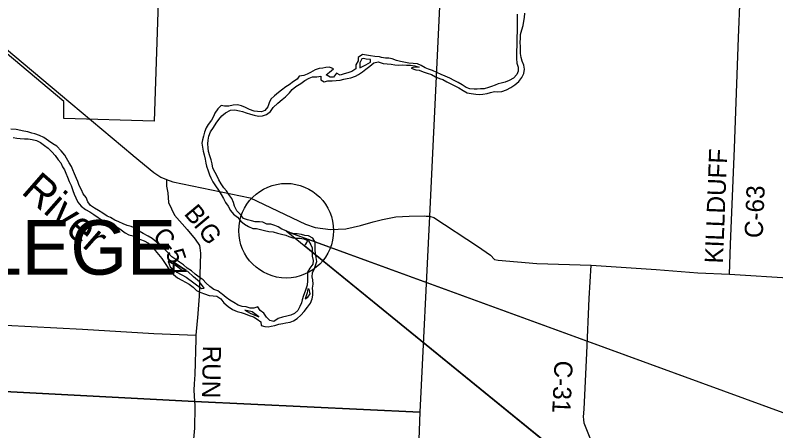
# Model space of a CAD drawing. Extents: x 41.3 to 81.6, y -19.3 to 2.7.
# Drawn here: x 46.925 to 48.932, y -1.162 to -0.064 of the extents above; entities that cross this region are included whole.
import ezdxf

# ---------------------------------------------------------------- set-up
doc = ezdxf.new("R2010")
doc.units = 0
for name, color, linetype in [('Default', 7, 'Continuous'), ('GM_X_Corporation', 7, 'Continuous'), ('GM_X_County_Road', 7, 'Continuous'), ('GM_X_County_Road_Text', 7, 'Continuous'), ('GM_X_Major_River', 7, 'Continuous'), ('GM_X_Major_River_Text', 7, 'Continuous'), ('GM_X_State_Route', 7, 'Continuous'), ('GM_X_Township', 7, 'Continuous'), ('GM_X_Township_Road', 7, 'Continuous'), ('GM_X_Township_Text', 7, 'Continuous')]:
    doc.layers.add(name, color=color, linetype=linetype)

msp = doc.modelspace()

# ---------------------------------------------------------------- linework, layer by layer
at = {"layer": 'Default'}
for p, q in [((47.6399, -0.6336), (50.5165, -2.9781)), ((47.6514, -0.6388), (50.5165, -1.6863))]:
    msp.add_line(p, q, dxfattribs=at)
msp.add_lwpolyline([(47.6983, -0.6559), (50.5165, -1.6863), (50.5165, -2.9781), (47.6883, -0.6731)], dxfattribs=at)
msp.add_circle((47.6399, -0.6336), 0.125, dxfattribs=at)
msp.add_arc((47.6399, -0.6336), 0.0625, 320.8199, 339.1082, dxfattribs=at)
at = {"layer": 'GM_X_Corporation'}
msp.add_lwpolyline([(46.584, 0.4876), (46.608, 0.4783), (46.619, 0.799), (47.3288, 0.7822), (47.2918, -0.3441), (47.053, -0.3369), (47.053, -0.2918), (46.8252, -0.1011), (46.7581, -0.0438), (46.7215, -0.0005), (46.7256, 0.0209), (46.722, 0.0646), (46.7171, 0.1029), (46.7053, 0.1736), (46.6837, 0.2398), (46.6465, 0.2782), (46.6014, 0.293), (46.6062, 0.436), (46.6004, 0.4311), (46.5985, 0.4242), (46.5815, 0.4287), (46.5709, 0.4515)], close=True, dxfattribs=at)
at = {"layer": 'GM_X_County_Road'}
for points in [[(48.8102, -0.7486), (48.813, -0.6703), (48.823, -0.4156), (48.8336, -0.1239), (48.8383, -0.0159), (48.8447, 0.1605), (48.8484, 0.2147), (48.8509, 0.225), (48.8521, 0.23), (48.8515, 0.235)], [(47.3243, -0.4981), (47.3242, -0.516), (47.3271, -0.5333), (47.3296, -0.5586), (47.3454, -0.5926), (47.3787, -0.6308), (47.3999, -0.6561), (47.4107, -0.6723), (47.4117, -0.679)], [(47.4117, -0.679), (47.4136, -0.6925), (47.41, -0.8064), (47.4058, -0.8639)], [(48.4513, -1.2042), (48.4266, -1.1421), (48.4254, -1.1325), (48.4248, -1.1257), (48.4262, -1.1052), (48.4333, -0.9576), (48.4399, -0.8126), (48.445, -0.7243)], [(47.4058, -0.8639), (47.4052, -0.8717), (47.4017, -0.91), (47.4013, -0.9199), (47.3989, -1.0139), (47.397, -1.0382), (47.3962, -1.0553), (47.3982, -1.085), (47.3987, -1.0945)], [(47.3987, -1.0945), (47.3989, -1.0986), (47.3981, -1.1557), (47.3902, -1.2438)]]:
    msp.add_lwpolyline(points, dxfattribs=at)
at = {"layer": 'GM_X_Major_River'}
for points in [[(47.8928, -0.1906), (47.8956, -0.1919), (47.9065, -0.1929), (47.9171, -0.1932), (47.927, -0.1952), (47.9369, -0.1965), (47.9475, -0.1953), (47.9574, -0.1959), (47.968, -0.196), (47.9795, -0.1976), (47.9907, -0.2012), (47.9745, -0.2024), (47.9697, -0.2045), (47.9824, -0.2081), (47.9905, -0.2091), (48.0016, -0.214), (48.0121, -0.2169), (48.023, -0.2208), (48.0342, -0.2273), (48.0444, -0.2315), (48.0531, -0.2341), (48.0636, -0.2402), (48.0726, -0.245), (48.085, -0.2508), (48.0959, -0.256), (48.1068, -0.2628), (48.1173, -0.2689), (48.1282, -0.2712), (48.1401, -0.2728), (48.1506, -0.2735), (48.1593, -0.2732), (48.1702, -0.2707), (48.1788, -0.2681), (48.1894, -0.2653), (48.1981, -0.2666), (48.2093, -0.2653), (48.2215, -0.2609), (48.2324, -0.2554), (48.2436, -0.2484), (48.2536, -0.2392), (48.2616, -0.2289), (48.2671, -0.2183), (48.2687, -0.2068), (48.2668, -0.1965), (48.263, -0.1859), (48.2602, -0.1757), (48.2586, -0.1651), (48.258, -0.1551), (48.258, -0.1471), (48.2577, -0.1362), (48.2581, -0.125), (48.2587, -0.1147), (48.2617, -0.1029), (48.2652, -0.0916), (48.2672, -0.0801), (48.2688, -0.0698), (48.2698, -0.0586)], [(48.2493, -0.0614), (48.2493, -0.0701), (48.2495, -0.0807), (48.2492, -0.0926), (48.2491, -0.1092), (48.2485, -0.1205), (48.2484, -0.1285), (48.2487, -0.1368), (48.2487, -0.1458), (48.248, -0.157), (48.248, -0.1788), (48.2489, -0.1907), (48.2521, -0.2013), (48.2524, -0.2122), (48.2485, -0.2205), (48.2398, -0.2301), (48.2283, -0.2365), (48.2177, -0.2407), (48.2071, -0.2435), (48.1991, -0.2454), (48.1911, -0.2492), (48.1821, -0.2524), (48.1741, -0.2553), (48.1625, -0.2588), (48.1523, -0.2587), (48.1443, -0.2594), (48.1363, -0.2593), (48.1247, -0.259), (48.1145, -0.2554), (48.104, -0.248), (48.0934, -0.2422), (48.0832, -0.2367), (48.072, -0.2309), (48.0595, -0.2254), (48.0489, -0.2209), (48.0377, -0.2154), (48.0262, -0.2106), (48.0154, -0.2067), (48.007, -0.2028), (47.9958, -0.1967), (47.9862, -0.1925), (47.9754, -0.1915), (47.9635, -0.1905), (47.9417, -0.1866), (47.9309, -0.1837), (47.9193, -0.1795), (47.911, -0.1778), (47.9017, -0.1775), (47.8918, -0.1755), (47.8861, -0.1741)], [(47.8861, -0.1741), (47.8736, -0.1728), (47.8627, -0.1715), (47.8515, -0.1693), (47.8413, -0.168), (47.8301, -0.1763), (47.8298, -0.1846), (47.824, -0.1955), (47.8237, -0.2061), (47.8134, -0.2125), (47.8029, -0.2163), (47.7929, -0.2189), (47.7827, -0.2227), (47.7725, -0.2172), (47.7651, -0.2281), (47.7555, -0.2278), (47.7456, -0.2214), (47.7543, -0.2143), (47.7648, -0.206), (47.7543, -0.2012), (47.7447, -0.2025), (47.7364, -0.204), (47.7271, -0.205), (47.7162, -0.2088), (47.7037, -0.2155), (47.6954, -0.2197), (47.6861, -0.2235), (47.6743, -0.2251), (47.6692, -0.2335), (47.6589, -0.2389), (47.6477, -0.2485), (47.6388, -0.2536), (47.6279, -0.2623), (47.6192, -0.268), (47.6093, -0.277), (47.5997, -0.2856)], [(47.8397, -0.1798), (47.8339, -0.1904), (47.8345, -0.2035), (47.8502, -0.1949)], [(47.8502, -0.1949), (47.8627, -0.1882), (47.8621, -0.1815), (47.8509, -0.1805), (47.8442, -0.1789), (47.8397, -0.1798)], [(47.6058, -0.3084), (47.6182, -0.2962), (47.6288, -0.2873), (47.6378, -0.2802), (47.649, -0.269), (47.6557, -0.2607), (47.6653, -0.2524), (47.6781, -0.245), (47.6893, -0.237), (47.7002, -0.2303), (47.7092, -0.2274), (47.7203, -0.2268), (47.7312, -0.2255), (47.7315, -0.2348), (47.7398, -0.24), (47.7501, -0.2377), (47.7613, -0.2371), (47.7718, -0.2368), (47.7827, -0.2359), (47.792, -0.2333), (47.8006, -0.2317), (47.8105, -0.2295), (47.8224, -0.2253), (47.831, -0.2209), (47.8412, -0.2138), (47.8499, -0.2071), (47.8604, -0.1991), (47.8713, -0.1898), (47.8822, -0.1869), (47.8928, -0.1906)], [(47.5997, -0.2856), (47.5952, -0.2959), (47.5917, -0.3061), (47.5837, -0.3161), (47.575, -0.3193), (47.5639, -0.3189), (47.5549, -0.3173), (47.5434, -0.3135), (47.5322, -0.308), (47.5223, -0.3038), (47.5114, -0.3006), (47.4996, -0.3015), (47.4881, -0.3047), (47.4769, -0.3041), (47.4679, -0.3031), (47.459, -0.3114), (47.4513, -0.3226), (47.4484, -0.3319), (47.4426, -0.3419), (47.4337, -0.3531), (47.4289, -0.3614), (47.424, -0.3729), (47.4215, -0.3835), (47.4192, -0.3931), (47.4176, -0.4024), (47.4192, -0.413), (47.4211, -0.4233), (47.4233, -0.4329), (47.4262, -0.4445), (47.4281, -0.4554), (47.4297, -0.4634), (47.4338, -0.4753), (47.4377, -0.4855), (47.4412, -0.4935), (47.4463, -0.5048), (47.4533, -0.5154), (47.4609, -0.5263), (47.4683, -0.5378), (47.474, -0.5484), (47.4801, -0.559), (47.4865, -0.569), (47.4932, -0.5799), (47.5005, -0.5898), (47.5111, -0.5975), (47.52, -0.6085), (47.5299, -0.6162), (47.5401, -0.6226), (47.5516, -0.6274), (47.5619, -0.6274), (47.5718, -0.6303), (47.5823, -0.6329), (47.5938, -0.6355), (47.6054, -0.6365), (47.6165, -0.6404), (47.6274, -0.6426), (47.6386, -0.6452), (47.6469, -0.6491), (47.6575, -0.6523), (47.6661, -0.6532), (47.6763, -0.6529), (47.6866, -0.6552), (47.6987, -0.6607), (47.7051, -0.6709), (47.7086, -0.679), (47.7083, -0.6892), (47.7082, -0.7005), (47.7111, -0.712), (47.7104, -0.7219), (47.7024, -0.7322), (47.6964, -0.7428), (47.6957, -0.7543), (47.6957, -0.7659), (47.695, -0.7771), (47.6928, -0.7857), (47.6899, -0.7937), (47.6857, -0.8046), (47.6822, -0.8159), (47.6799, -0.8239), (47.6758, -0.8341), (47.6706, -0.8444), (47.6617, -0.8527), (47.6518, -0.8569), (47.6415, -0.8597), (47.6303, -0.8623), (47.6191, -0.8655), (47.6073, -0.8735), (47.5964, -0.8706), (47.5875, -0.8616), (47.5811, -0.8513), (47.5709, -0.8446), (47.5651, -0.8346), (47.5546, -0.8385), (47.545, -0.8384), (47.5344, -0.8349), (47.5239, -0.8336), (47.5127, -0.8301), (47.5018, -0.8233), (47.491, -0.8175), (47.4811, -0.8098), (47.4708, -0.8011), (47.468, -0.7995)], [(47.457, -0.8068), (47.467, -0.8136), (47.4756, -0.8242), (47.4865, -0.8342), (47.4983, -0.8416), (47.5101, -0.8467), (47.521, -0.8493), (47.5319, -0.8529), (47.5424, -0.8577), (47.5533, -0.8612), (47.5635, -0.867), (47.5728, -0.8747), (47.5734, -0.884), (47.5836, -0.8863), (47.5922, -0.8873), (47.6006, -0.8857), (47.6095, -0.8838), (47.6204, -0.8809), (47.6306, -0.879), (47.6389, -0.8774), (47.6501, -0.8751), (47.6591, -0.8716), (47.669, -0.8659), (47.6783, -0.8566), (47.6876, -0.8467), (47.6959, -0.8354), (47.7039, -0.8246), (47.7081, -0.814), (47.7103, -0.8037), (47.71, -0.7935), (47.7097, -0.7854), (47.7113, -0.7752), (47.7101, -0.7636), (47.7082, -0.7556), (47.7091, -0.745), (47.7149, -0.7338), (47.7184, -0.7232), (47.7204, -0.7152), (47.7191, -0.7046), (47.7175, -0.694), (47.7159, -0.6838), (47.716, -0.6642), (47.7105, -0.6533), (47.6984, -0.6469), (47.6888, -0.6459), (47.6802, -0.644), (47.669, -0.6417), (47.6607, -0.6414), (47.6514, -0.6388), (47.6399, -0.6336), (47.6284, -0.6298), (47.6191, -0.6234), (47.6102, -0.6201), (47.599, -0.616), (47.5891, -0.6159), (47.5779, -0.6111), (47.5692, -0.6098), (47.5581, -0.6098), (47.5481, -0.6079), (47.5373, -0.6046), (47.5274, -0.6014), (47.5194, -0.5908), (47.5098, -0.5809), (47.5037, -0.569), (47.5009, -0.5594), (47.4961, -0.5485), (47.4888, -0.5375), (47.4824, -0.5279), (47.4757, -0.5199), (47.468, -0.5096), (47.4623, -0.4987), (47.4575, -0.4894), (47.4521, -0.4794), (47.4466, -0.4682), (47.4441, -0.457), (47.4419, -0.4461), (47.4387, -0.4361), (47.4352, -0.4246), (47.4336, -0.4146), (47.433, -0.4041), (47.4343, -0.3941), (47.4359, -0.3835), (47.4404, -0.372), (47.448, -0.3605), (47.4554, -0.3496), (47.4621, -0.34), (47.4698, -0.3297), (47.4801, -0.322), (47.4929, -0.315), (47.5047, -0.314), (47.5165, -0.3166), (47.5248, -0.3189), (47.5341, -0.3224), (47.5456, -0.326), (47.5549, -0.3285), (47.5664, -0.3305), (47.5773, -0.3302), (47.5882, -0.3263), (47.5984, -0.3183), (47.6058, -0.3084)], [(47.1235, -0.5672), (47.1159, -0.5569), (47.112, -0.546), (47.1041, -0.5357), (47.0999, -0.5254), (47.0932, -0.5145), (47.0897, -0.5036), (47.0862, -0.4956), (47.0808, -0.4837), (47.0766, -0.4725), (47.0735, -0.4642), (47.0674, -0.4539), (47.0604, -0.442), (47.0553, -0.434), (47.046, -0.4227), (47.0348, -0.4105), (47.0243, -0.4038), (47.0125, -0.3958), (47.0003, -0.3871), (46.9888, -0.3816), (46.9767, -0.3774), (46.9684, -0.3755), (46.9578, -0.3723), (46.9473, -0.3703), (46.9268, -0.3665), (46.9134, -0.3655)], [(46.9188, -0.3876), (46.9287, -0.3892), (46.938, -0.3896), (46.9492, -0.3909), (46.9584, -0.3912), (46.969, -0.3922), (46.9808, -0.3948), (46.9914, -0.4009), (47.0019, -0.4083), (47.0112, -0.4156), (47.0217, -0.4253), (47.0303, -0.4352), (47.038, -0.4461), (47.0447, -0.4545), (47.0498, -0.4644), (47.0543, -0.4725), (47.0581, -0.4811), (47.0629, -0.4924), (47.0673, -0.5036), (47.0721, -0.5142), (47.0766, -0.527), (47.0804, -0.537), (47.0842, -0.5466)], [(47.0842, -0.5466), (47.0896, -0.5578), (47.0989, -0.5691), (47.1098, -0.5771), (47.1213, -0.5835), (47.1325, -0.5909), (47.1433, -0.5986), (47.1516, -0.6038), (47.1615, -0.6092), (47.1718, -0.6144), (47.1823, -0.6192), (47.1925, -0.6237), (47.2047, -0.6311), (47.2149, -0.6391), (47.2248, -0.6443), (47.2357, -0.6475), (47.2456, -0.6536), (47.2555, -0.6568), (47.2654, -0.6604), (47.2766, -0.6662), (47.2858, -0.6755), (47.2941, -0.6858), (47.3031, -0.6967), (47.3114, -0.7069), (47.319, -0.7175), (47.3261, -0.7284), (47.3328, -0.7394), (47.3427, -0.749), (47.3532, -0.7583), (47.3641, -0.7644), (47.3743, -0.7692), (47.3839, -0.775), (47.3941, -0.7831), (47.4027, -0.7917), (47.4146, -0.7969), (47.4245, -0.8007), (47.4366, -0.8049), (47.4472, -0.8056), (47.457, -0.8068)], [(47.468, -0.7995), (47.459, -0.7921), (47.4488, -0.7889), (47.4386, -0.7812), (47.428, -0.7716), (47.4207, -0.7632), (47.4101, -0.7562), (47.3999, -0.7481), (47.39, -0.7398), (47.3788, -0.7327), (47.3692, -0.7234), (47.3581, -0.717), (47.3485, -0.7099), (47.3379, -0.7022), (47.3287, -0.6919), (47.3185, -0.6826), (47.3079, -0.6729), (47.2971, -0.663), (47.2862, -0.6543), (47.2753, -0.6482), (47.2625, -0.6408), (47.252, -0.6347), (47.2411, -0.6267), (47.2306, -0.6228), (47.22, -0.6196), (47.2095, -0.6154), (47.1977, -0.6103), (47.1878, -0.6054), (47.1759, -0.599), (47.1673, -0.5948), (47.1555, -0.5871), (47.1443, -0.5804), (47.1341, -0.5736), (47.1235, -0.5672)], [(47.328, -0.715), (47.3334, -0.7291), (47.351, -0.7432), (47.3756, -0.7561), (47.396, -0.7709), (47.4162, -0.786), (47.4235, -0.7857)], [(47.4235, -0.7857), (47.4111, -0.7683), (47.3951, -0.7555), (47.3804, -0.741), (47.3657, -0.7391), (47.3504, -0.7269), (47.335, -0.7182), (47.328, -0.715)], [(47.6966, -0.7873), (47.695, -0.7979), (47.6899, -0.8136), (47.6972, -0.8095)], [(47.6972, -0.8095), (47.7033, -0.8008), (47.7008, -0.7877), (47.6966, -0.7873)], [(47.5306, -0.8439), (47.5446, -0.8519), (47.5673, -0.8609)], [(47.5673, -0.8609), (47.5504, -0.8477), (47.5306, -0.8439)]]:
    msp.add_lwpolyline(points, dxfattribs=at)
at = {"layer": 'GM_X_State_Route'}
for points in [[(46.8196, -0.0857), (46.8201, -0.0863), (46.824, -0.0896), (47.0441, -0.2738), (47.2355, -0.4341)], [(47.2355, -0.4341), (47.2362, -0.4347), (47.2903, -0.48), (47.3086, -0.4918), (47.3243, -0.4981), (47.3403, -0.5045), (47.545, -0.5463), (47.691, -0.6165), (47.716, -0.6248), (47.7566, -0.6304), (47.7972, -0.6284), (47.8358, -0.6199), (47.8696, -0.6105)], [(47.8696, -0.6105), (47.8938, -0.6037), (47.9293, -0.5965), (47.9645, -0.5948), (48.0058, -0.5943), (48.0094, -0.5951), (48.0177, -0.5949), (48.0295, -0.5989), (48.1451, -0.6746), (48.1793, -0.6983), (48.1897, -0.7097), (48.199, -0.7113), (48.3018, -0.7199), (48.445, -0.7243), (48.6163, -0.736), (48.7268, -0.7446), (48.8102, -0.7486), (48.9777, -0.7586)]]:
    msp.add_lwpolyline(points, dxfattribs=at)
at = {"layer": 'GM_X_Township'}
for points in [[(46.6323, 1.082), (46.9356, 1.0671), (47.0053, 1.0645), (47.0849, 1.0611), (47.1126, 1.0599), (47.341, 1.0494), (47.5073, 1.0425), (48.1003, 1.0179), (48.0986, 0.982), (48.0693, 0.447), (48.0597, 0.2729), (48.0177, -0.5949), (47.9927, -1.1134), (47.3982, -1.085), (46.8967, -1.0581)], [(49.8429, 0.9122), (48.8731, 0.9493), (48.8673, 0.9496), (48.8494, 0.9506), (48.7166, 0.9552), (48.2508, 0.9768), (48.0986, 0.982), (48.0597, 0.2729), (48.0177, -0.5949), (47.9927, -1.1134), (47.9826, -1.3785), (47.9474, -2.0041), (47.9161, -2.7711), (47.8928, -3.2748), (47.902, -3.2801), (47.9094, -3.2815), (47.9235, -3.2831), (48.0099, -3.2846), (48.5864, -3.309), (48.645, -3.3113), (49.6175, -3.339)], [(46.8967, -1.0581), (47.3982, -1.085), (47.9927, -1.1134), (47.9826, -1.3785)]]:
    msp.add_lwpolyline(points, dxfattribs=at)
at = {"layer": 'GM_X_Township_Road'}
msp.add_lwpolyline([(46.8974, -1.0547), (46.8975, -1.054), (46.8978, -1.043), (46.8972, -0.9028), (46.8994, -0.8836), (47.1019, -0.8938), (47.2907, -0.9048), (47.4017, -0.91)], dxfattribs=at)

# ---------------------------------------------------------------- texts
at = {"layer": 'GM_X_County_Road_Text'}
for s, rotation, p in [('KILLDUFF', 87.7266, (48.7924, -0.7208)), ('C-63', 87.5998, (48.8974, -0.6539)), ('B', 310.1424, (47.3683, -0.5895)), ('I', 309.8266, (47.3937, -0.6196)), ('G', 304.8419, (47.4056, -0.6339)), ('C', 310.3473, (47.2851, -0.6499)), ('5', 288.9961, (47.321, -0.6908)), ('-', 310.3494, (47.3106, -0.6799)), ('4', 268.7874, (47.33, -0.7144)), ('RUN', 269.0265, (47.42, -0.9369)), ('C-31', 267.2576, (48.3485, -0.9759))]:
    msp.add_text(s, height=0.048, rotation=rotation, dxfattribs=at).set_placement(p)
at = {"layer": 'GM_X_Major_River_Text'}
msp.add_text('River', height=0.08, rotation=318.8029, dxfattribs=at).set_placement((46.9379, -0.5333))
at = {"layer": 'GM_X_Township_Text'}
msp.add_text('COLLEGE', height=0.144, rotation=0, dxfattribs=at).set_placement((46.4388, -0.7497))

doc.saveas('drawing.dxf')
